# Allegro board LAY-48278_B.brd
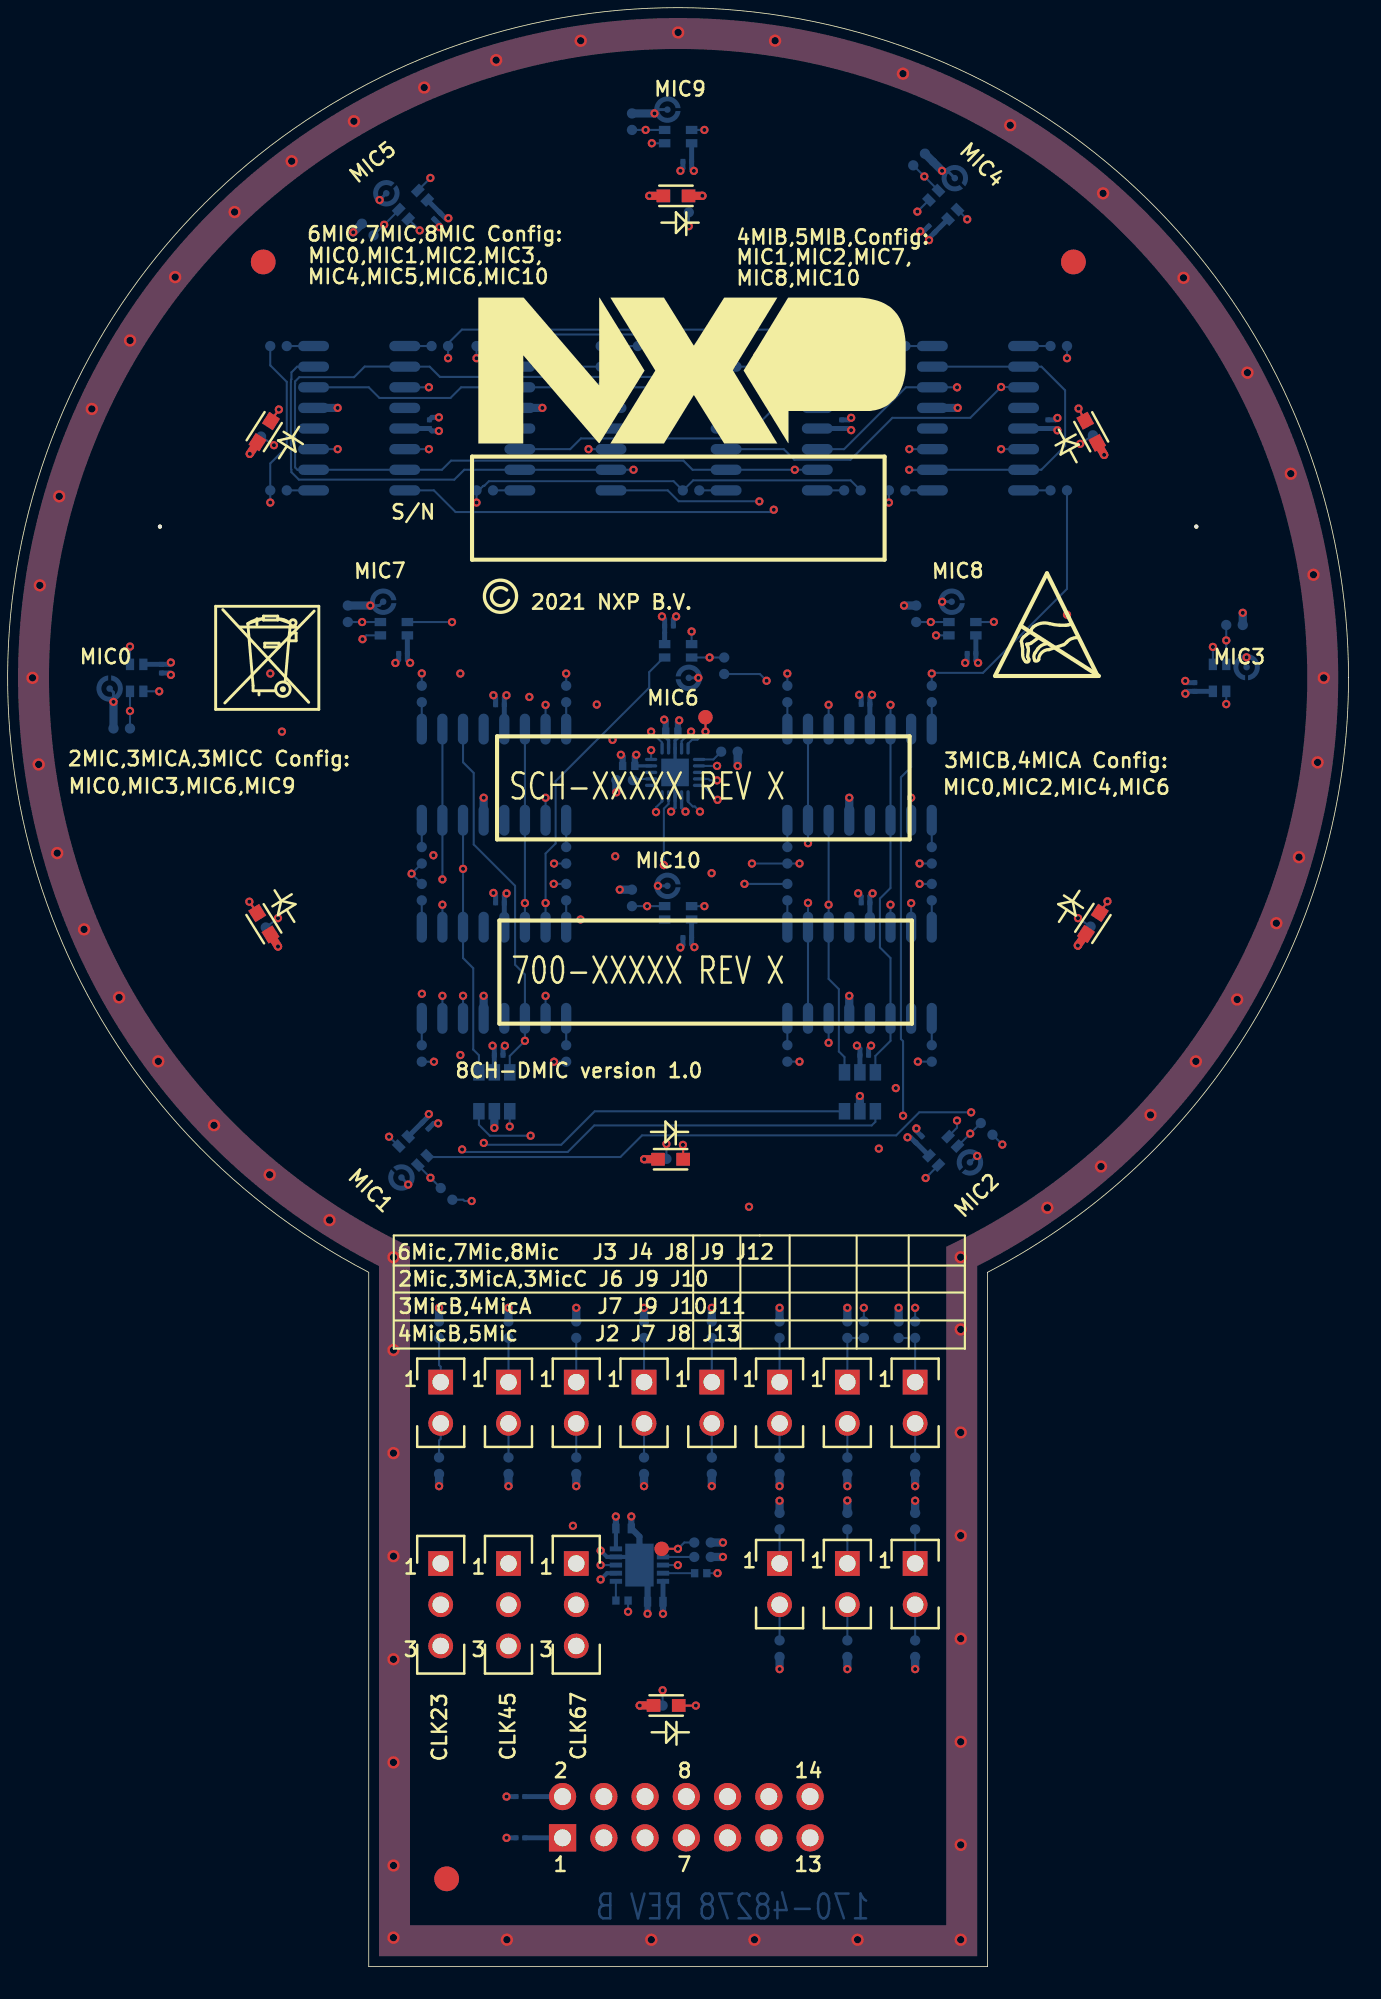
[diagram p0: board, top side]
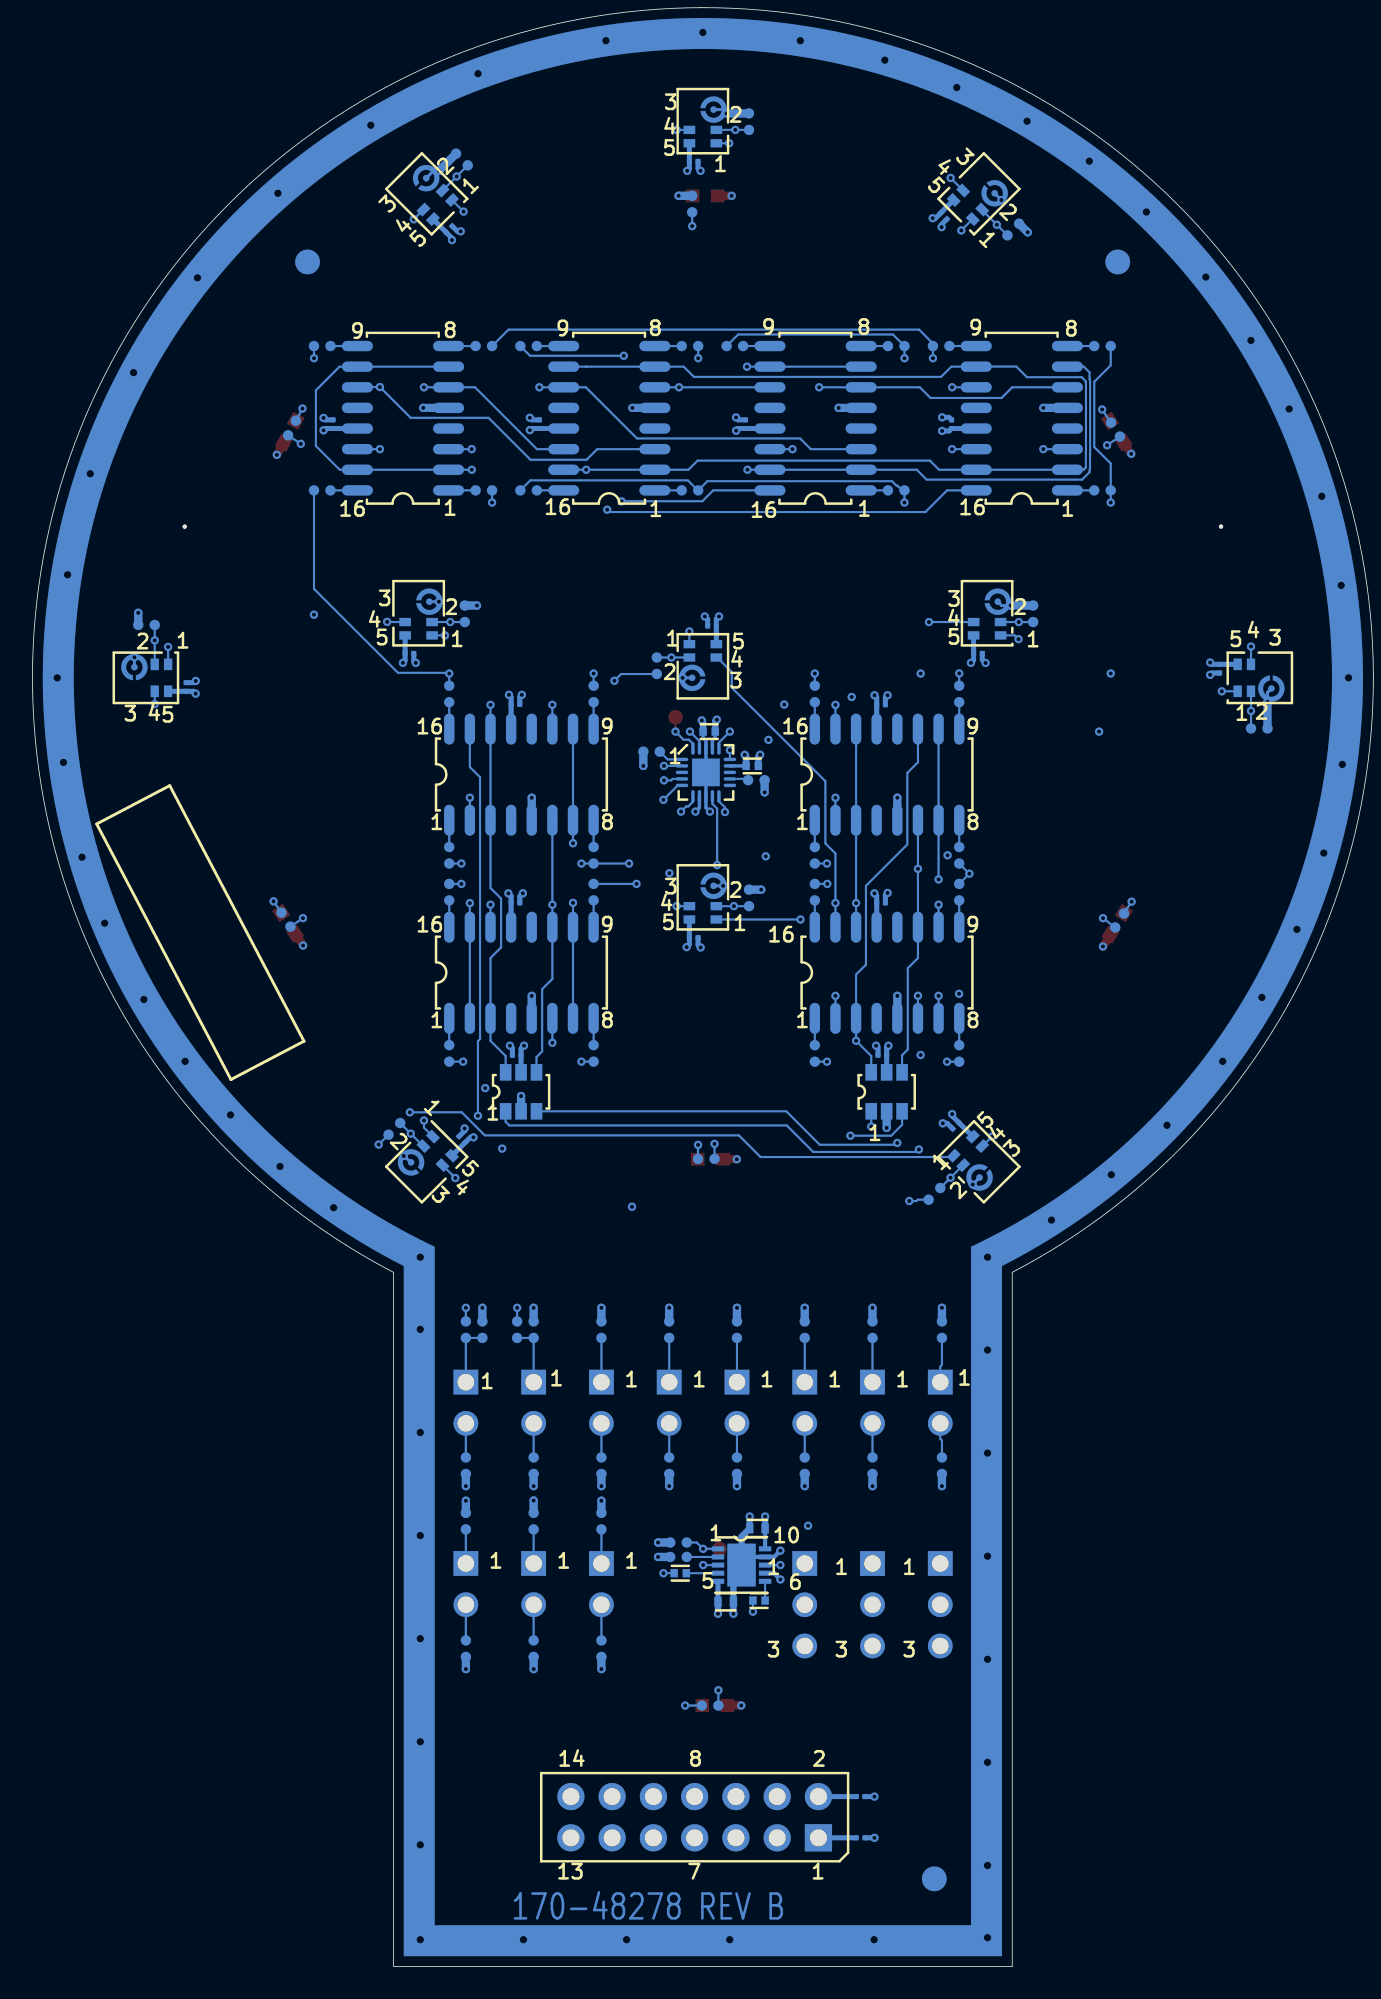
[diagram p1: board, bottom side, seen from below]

Outline 62.69 x 114.66 mm; copper layers: TOP, L2_GND_1, L3_INNER_1, L4_PWR_1, L5_PWR_2, L6_INNER_2, L7_GND_2, BOTTOM. Coordinates in mm from the lower left corner of the outline.
Outline path: 2.37,42.76 2.37,0 40.47,0 40.47,42.76 arc(56.7,57.96) 62.69,79.38 arc(0,114.66) 2.37,42.76

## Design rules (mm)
constraint set DEFAULT: min track width 0.127

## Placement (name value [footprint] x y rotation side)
C1  0.1uF  [0201_CC]  11.7 7.93 180 bottom
C2  0.1uF  [0201_CC]  11.7 10.47 180 bottom
C3  0.1uF  [0201_CC]  -10.4 79.94 270 bottom
C4  0.1uF  [0201_CC]  39.48 80.88 180 bottom
C5  0.1uF  [0201_CC]  5.85 51.79 315 bottom
C6  0.1uF  [0201_CC]  21.98 111.19 180 bottom
C7  0.1uF  [0201_CC]  36.24 50.94 45 bottom
C8  0.1uF  [0201_CC]  53.23 78.81 90 bottom
C9  0.1uF  [0201_CC]  21.98 63.38 180 bottom
C10  0.1uF  [0201_CC]  37.04 107.01 135 bottom
C11  0.1uF  [0201_CC]  6.58 107.82 225 bottom
C12  0.1uF  [0201_CC]  20.85 82.57 0 bottom
C13  0.1uF  [0201_CC]  4.48 80.88 180 bottom
C14  0.1uF  [0201_CC]  32.96 77.74 180 bottom
C15  0.1uF  [0201_CC]  44.19 95 90 bottom
C16  0.1uF  [0201_CC]  32.88 56.13 0 bottom
C17  0.1uF  [0201_CC]  31.49 95 90 bottom
C18  0.1uF  [0201_CC]  32.96 65.52 180 bottom
C19  0.1uF  [0201_CC]  10.37 56.13 0 bottom
C20  0.1uF  [0201_CC]  6.1 95 90 bottom
C21  0.1uF  [0201_CC]  10.45 65.52 180 bottom
C22  0.1uF  [0201_CC]  18.79 95 90 bottom
C23  0.1uF  [0201_CC]  10.45 77.72 180 bottom
C24  1.0UF  [0402_CC]  18.38 73.95 180 bottom
C25  1.0UF  [0402_CC]  21.03 76.06 0 bottom
C26  10uF  [CC0402_TOL0P2]  18.06 26.98 0 bottom
C27  10uF  [CC0402_TOL0P2]  20.01 22.46 180 bottom
C28  1.0UF  [0402_CC]  17.96 22.54 0 bottom
C29  1.0UF  [0402_CC]  22.81 24.23 0 bottom
D1  BLUE  [LED_0603]  -4.09 64.23 121.9 top
D2  BLUE  [LED_0603]  20.95 49.72 0 top
D3  BLUE  [LED_0603]  46.95 64.25 56.7 top
D4  BLUE  [LED_0603]  46.85 94.53 118.6 top
D5  BLUE  [LED_0603]  21.28 109.06 0 top
D6  BLUE  [LED_0603]  -4.07 94.54 57.5 top
D7  RED  [LED_0603]  20.68 16.08 0 top
J1  CON 2X7  [CON_2X7_SKT_2P54_TH]  14.3 7.93 0 bottom
J2  HDR 1X2  [HDR102]  27.66 24.82 0 top
J3  HDR 1X2  [HDR102]  31.84 24.83 0 top
J4  HDR 1X2  [HDR102]  36.01 24.83 0 top
J5  HDR_1X3  [HDR103]  6.8 24.82 0 top
J6  HDR 1X2  [HDR102]  6.8 35.99 0 top
J7  HDR 1X2  [HDR102]  10.97 35.99 0 top
J8  HDR 1X2  [HDR102]  15.14 35.99 0 top
J9  HDR 1X2  [HDR102]  19.32 35.99 0 top
J10  HDR 1X2  [HDR102]  23.49 35.99 0 top
J11  HDR 1X2  [HDR102]  27.66 35.99 0 top
J12  HDR 1X2  [HDR102]  31.84 35.99 0 top
J13  HDR 1X2  [HDR102]  36.01 35.99 0 top
J14  HDR_1X3  [HDR103]  10.97 24.82 0 top
J15  HDR_1X3  [HDR103]  15.14 24.82 0 top
NOREF  -  []  54.34 78.54 0 top
NOREF#2  -  []  21.42 79.38 90 top
NOREF#3  -  []  40.29 85.15 90 top
NOREF#4  -  []  60.26 80.75 90 top
NOREF#5  -  []  4.12 47.32 0 top
NOREF#6  -  []  18.66 27.33 90 top
NOREF#7  -  []  38.04 107.63 90 top
NOREF#8  -  []  22.7 72.75 90 top
NOREF#9  -  []  22.25 113.12 90 top
NOREF#10  -  []  22.25 65.31 90 top
NOREF#11  -  []  24.73 72.05 90 top
NOREF#12  -  []  21.73 72.05 0 top
NOREF#13  -  []  8.73 86.65 0 top
NOREF#14  -  []  4.75 81.99 90 top
NOREF#15  -  []  58.74 70.37 0 top
NOREF#16  -  []  31.19 1.58 90 top
NOREF#17  -  []  20.43 75.02 0 top
NOREF#18  -  []  38.62 108.21 90 top
NOREF#19  -  []  27 10.47 0 top
NOREF#20  -  [unnamed#2]  -4.13 104.99 0 top
NOREF#21  -  []  -408.7 -274.72 0 top
NOREF#22  -  []  -11.13 104.76 0 top
NOREF#23  -  []  38.09 82.81 0 top
NOREF#24  -  []  12.65 1.58 0 top
NOREF#25  -  []  22.79 115.47 90 top
NOREF#26  -  []  3.92 49.06 90 top
NOREF#27  -  []  6.87 47.32 90 top
NOREF#28  -  []  9.11 93.83 0 top
NOREF#29  -  []  20.59 80.63 90 top
NOREF#30  -  []  21.63 75.02 0 top
NOREF#31  -  []  2.17 109.48 0 top
NOREF#32  -  []  2.37 0 0 top
NOREF#33  -  []  20.59 113.12 0 top
NOREF#34  -  []  40.95 79.49 0 top
NOREF#35  -  []  5.97 108.81 90 top
NOREF#36  -  []  55.16 78.54 90 top
NOREF#37  -  []  -7.06 77.43 0 top
NOREF#38  -  []  37.44 49.36 0 top
NOREF#39  -  []  -376.32 243.82 0 top
NOREF#40  -  [unnamed#2]  53.32 88.69 0 top
NOREF#41  -  []  17.59 26.98 0 top
NOREF#42  -  []  20.04 67.65 0 top
NOREF#43  -  []  22.79 67.65 90 top
NOREF#44  -  []  38.72 111.43 0 top
NOREF#45  -  []  21.81 22.11 90 top
NOREF#46  -  []  37.44 109.39 0 top
NOREF#47  -  [unnamed#2]  45.76 104.99 0 top
NOREF#48  -  []  4.21 50.54 90 top
NOREF#49  -  []  22.79 78.28 0 top
NOREF#50  -  []  20.61 22.11 0 top
NOREF#51  -  []  25.54 78.28 90 top
NOREF#52  -  []  3.09 82.81 0 top
NOREF#53  -  []  4.75 82.81 90 top
NOREF#54  -  []  4.92 109.48 90 top
NOREF#55  -  []  19.54 22.46 0 top
NOREF#56  -  []  22.7 72.75 90 top
NOREF#57  -  []  4.21 108.21 0 top
NOREF#58  -  []  -13.58 79.38 90 top
NOREF#59  -  []  -12.33 78.54 90 top
NOREF#60  -  [unnamed#2]  -10.49 88.69 0 top
NOREF#61  -  []  2.54 85.15 0 top
NOREF#62  -  []  37.54 85.15 0 top
NOREF#63  -  []  -12.33 80.21 0 top
NOREF#64  -  []  7.17 5.4 0 top
NOREF#65  -  []  5.39 109.39 90 top
NOREF#66  -  []  22.25 112.3 90 top
NOREF#67  -  []  40.47 0 90 top
NOREF#68  -  []  -23.89 -50.56 0 top
NOREF#69  -  []  22.25 64.49 90 top
NOREF#70  -  []  37.44 49.36 90 top
NOREF#71  -  []  -11.92 78 90 top
NOREF#72  -  []  2.37 0 0 top
NOREF#73  -  []  20.59 65.31 0 top
NOREF#74  -  []  38.92 49.06 90 top
NOREF#75  -  []  7.17 5.4 0 top
NOREF#76  -  []  40.66 49.27 0 top
NOREF#77  -  []  10.48 84.38 0 top
NOREF#78  -  []  17.46 27.33 0 top
NOREF#79  -  []  7.17 5.4 0 top
NOREF#80  -  []  -14.67 78 0 top
NOREF#81  -  []  39.75 82.81 90 top
NOREF#82  -  []  57.51 80.75 0 top
NOREF#83  -  []  43.41 49.27 90 top
NOREF#84  -  []  20.04 115.47 0 top
NOREF#85  -  []  41.47 111.43 90 top
NOREF#86  -  []  39.75 81.99 90 top
NOREF#87  -  []  55.16 78.54 90 top
NOREF#88  -  []  29.54 7.93 90 top
NOREF#89  -  []  5.29 85.15 90 top
NOREF#90  -  []  10.41 58.08 0 top
NOREF#91  -  []  2.37 0 0 top
NOREF#92  -  []  14.3 10.47 0 top
NOREF#93  -  [unnamed#2]  7.17 5.4 0 top
NOREF#94  -  []  4.21 50.54 0 top
NOREF#95  -  []  10.27 69.42 0 top
NOREF#96  -  []  20.59 80.63 0 top
NOREF#97  -  [unnamed#2]  7.17 5.4 180 bottom
NOREF#98  -  [unnamed#2]  -4.13 104.99 180 bottom
NOREF#99  -  []  58.74 70.37 242.3 bottom
NOREF#100  -  [unnamed#2]  45.76 104.99 180 bottom
R1  100K  [RC0402_25]  27.66 19.58 90 bottom
R2  0  [RC0402_25]  -12.84 76.26 0 bottom
R3  0  [RC0402_25]  7.16 47.59 135 bottom
R4  0  [RC0402_25]  36.07 83.32 270 bottom
R5  0  [RC0402_25]  18.58 113.63 270 bottom
R6  1K  [RC0402_25]  27.66 27.43 90 bottom
R7  100K  [RC0402_25]  31.84 19.58 90 bottom
R8  0  [RC0402_25]  40.41 51.59 135 bottom
R9  0  [RC0402_25]  55.67 82.63 180 bottom
R10  0  [RC0402_25]  18.58 65.82 270 bottom
R11  1K  [RC0402_25]  31.84 27.43 90 bottom
R12  0  [RC0402_25]  36.25 111.3 225 bottom
R13  0  [RC0402_25]  2.31 106.99 315 bottom
R14  100K  [RC0402_25]  36.01 19.58 90 bottom
R15  0  [RC0402_25]  24.25 80.12 90 bottom
R16  0  [RC0402_25]  1.08 83.32 270 bottom
R17  1K  [RC0402_25]  36.01 27.43 90 bottom
R18  100K  [RC0402_25]  6.7 39.23 270 bottom
R19  100K  [RC0402_25]  10.97 39.23 270 bottom
R20  100K  [RC0402_25]  15.14 39.23 270 bottom
R21  100K  [RC0402_25]  19.32 39.23 270 bottom
R22  0  [RC0402_25]  6.74 99.81 180 bottom
R23  0  [RC0402_25]  28.14 78.38 270 bottom
R24  0  [RC0402_25]  34.9 99.81 0 bottom
R25  0  [RC0402_25]  44.85 99.81 180 bottom
R26  0  [RC0402_25]  44.85 90.92 180 bottom
R27  0  [RC0402_25]  34.9 90.92 0 bottom
R28  0  [RC0402_25]  37.03 78.38 270 bottom
R29  0  [RC0402_25]  37.03 68.45 90 bottom
R30  0  [RC0402_25]  14.52 78.38 270 bottom
R31  0  [RC0402_25]  37.03 56.24 90 bottom
R32  1K  [RC0402_25]  10.97 30.85 270 bottom
R33  1K  [RC0402_25]  6.7 30.85 270 bottom
R34  1K  [RC0402_25]  15.14 30.85 270 bottom
R35  1K  [RC0402_25]  19.32 30.85 270 bottom
R36  100K  [RC0402_25]  23.49 39.23 270 bottom
R37  100K  [RC0402_25]  27.66 39.23 270 bottom
R38  100K  [RC0402_25]  31.84 39.23 270 bottom
R39  100K  [RC0402_25]  34.99 39.23 270 bottom
R40  0  [RC0402_25]  22.21 99.81 0 bottom
R41  0  [RC0402_25]  32.15 99.81 180 bottom
R42  0  [RC0402_25]  32.15 90.92 180 bottom
R43  0  [RC0402_25]  -3.19 99.81 0 bottom
R44  0  [RC0402_25]  9.51 99.81 0 bottom
R45  0  [RC0402_25]  -3.19 90.92 0 bottom
R46  0  [RC0402_25]  14.52 66.17 270 bottom
R47  0  [RC0402_25]  28.14 66.17 270 bottom
R48  0  [RC0402_25]  22.21 90.92 0 bottom
R49  0  [RC0402_25]  36.01 39.23 90 bottom
R50  0  [RC0402_25]  19.44 99.81 180 bottom
R51  0  [RC0402_25]  5.63 56.24 90 bottom
R52  0  [RC0402_25]  9.51 90.92 0 bottom
R53  0  [RC0402_25]  14.52 68.45 90 bottom
R54  0  [RC0402_25]  32.85 39.23 90 bottom
R55  0  [RC0402_25]  5.63 78.38 270 bottom
R56  0  [RC0402_25]  28.14 68.45 90 bottom
R57  0  [RC0402_25]  28.14 56.24 90 bottom
R58  0  [RC0402_25]  5.63 66.17 270 bottom
R59  0  [RC0402_25]  37.03 66.17 270 bottom
R60  1K  [RC0402_25]  23.49 30.85 270 bottom
R61  1K  [RC0402_25]  27.66 30.85 270 bottom
R62  0  [RC0402_25]  5.63 68.45 90 bottom
R63  0  [RC0402_25]  14.52 56.24 90 bottom
R64  1K  [RC0402_25]  36.01 30.85 270 bottom
R65  1K  [RC0402_25]  31.84 30.85 270 bottom
R66  330  [RC0402_25]  -4.24 64.43 301.9 bottom
R67  330  [RC0402_25]  21.21 49.75 180 bottom
R68  330  [RC0402_25]  47.09 64.48 237.3 bottom
R69  330  [RC0402_25]  46.72 94.76 298 bottom
R70  330  [RC0402_25]  22.07 108.56 270 bottom
R71  330  [RC0402_25]  -3.99 94.66 237.5 bottom
R72  510  [RC0402_25]  20.97 16.07 180 bottom
R73  100K  [RC0402_25]  24.57 74.83 180 bottom
R74  100K  [RC0402_25]  18.12 73.07 180 bottom
R75  100K  [RC0402_25]  22.92 26.12 0 bottom
R76  100K  [RC0402_25]  22.92 25.23 180 bottom
TP1  TP_35MIL  [TESTPOINT_35MIL]  23.1 76.95 0 top
TP2  TP_35MIL  [TESTPOINT_35MIL]  20.4 25.73 0 top
U1  SPH0641LM4H-1  [MIC5_3P6X2P75MM]  -12.87 79.38 90 bottom
U2  SPH0641LM4H-1  [MIC5_3P6X2P75MM]  38.92 83.35 0 bottom
U3  SPH0641LM4H-1  [MIC5_3P6X2P75MM]  4.42 49.57 135 bottom
U4  SPH0641LM4H-1  [MIC5_3P6X2P75MM]  21.42 113.67 0 bottom
U5  SPH0641LM4H-1  [MIC5_3P6X2P75MM]  38.41 49.57 225 bottom
U6  SPH0641LM4H-1  [MIC5_3P6X2P75MM]  55.71 79.38 270 bottom
U7  SPH0641LM4H-1  [MIC5_3P6X2P75MM]  21.42 65.85 0 bottom
U8  SPH0641LM4H-1  [MIC5_3P6X2P75MM]  38.41 109.18 315 bottom
U9  SPH0641LM4H-1  [MIC5_3P6X2P75MM]  4.42 109.18 45 bottom
U10  SPH0641LM4H-1  [MIC5_3P6X2P75MM]  21.42 80.08 180 bottom
U11  SPH0641LM4H-1  [MIC5_3P6X2P75MM]  3.92 83.35 0 bottom
U12  ADG711  [SO16-25X75]  39.89 95.37 90 bottom
U13  ADG711  [SO16-25X75]  32.59 73.42 180 bottom
U14  NL27WZ16DTT1G  [TSOP6_0P95_1P7X3P1]  32.61 53.88 90 bottom
U15  ADG711  [SO16-25X75]  27.19 95.37 90 bottom
U16  ADG711  [SO16-25X75]  32.59 61.22 180 bottom
U17  NL27WZ16DTT1G  [TSOP6_0P95_1P7X3P1]  10.1 53.88 90 bottom
U18  ADG711  [SO16-25X75]  1.79 95.37 90 bottom
U19  ADG711  [SO16-25X75]  10.08 61.22 180 bottom
U20  ADG711  [SO16-25X75]  14.49 95.37 90 bottom
U21  ADG711  [SO16-25X75]  10.08 73.42 180 bottom
U22  SX1502I087TRT  [QFN20_0P4_3X3_EP067]  21.23 73.55 180 bottom
U35  MCP1256T-E/MF  [DFN_10_0P5_3X3]  19.04 24.73 180 bottom

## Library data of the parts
C1-C29 = CAP_NP
D1-D7 = LED
J1 = CONN_HDR_7X2
J2-J4 J6-J13 = CONN_HDR_2X1
J5 J14 J15 = CONN_HDR_3X1
R1-R76 = RES
TP1 TP2 = T POINT R: Tolerance: TOLERANCE; User Part Number: 510-75618
U1-U11 = MIC_SPH0641LM4H-1_5P
U12 U13 U15 U16 U18-U21 = DG711
U14 U17 = NL27WZ16_TSOP_6P
U22 = SX1502_QFN_20P
U35 = MCP1256_DFN10

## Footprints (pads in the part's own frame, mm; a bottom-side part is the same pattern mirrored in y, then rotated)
0201_CC
  rect 0.305x0.305 smd: 1(-0.267,0) 2(0.267,0)
0402_CC
  rect 0.457x0.508 smd: 1(-0.375,0) 2(0.375,0)
CC0402_TOL0P2
  rect 0.457x0.61 smd: 1(-0.475,0) 2(0.475,0)
CON_2X7_SKT_2P54_TH
  rect 1.676x1.676 hole 1.041: 1(0,0)
  round 1.676 hole 1.041: 2(0,-2.54) 3(2.54,0) 4(2.54,-2.54) 5(5.08,0) 6(5.08,-2.54) 7(7.62,0) 8(7.62,-2.54) 9(10.16,0) 10(10.16,-2.54) 11(12.7,0) 12(12.7,-2.54) 13(15.24,0) 14(15.24,-2.54)
DFN_10_0P5_3X3
  rect 0.762x0.305 smd: 1(-1.45,1) 2(-1.45,0.5) 3(-1.45,0) 4(-1.45,-0.5) 5(-1.45,-1) 6(1.45,-1) 7(1.45,-0.5) 8(1.45,0) 9(1.45,0.5) 10(1.45,1)
  rect 1.753x2.642 smd: 11(0,0)
HDR102
  rect 1.524x1.524 hole 1.016: 1(0,0)
  round 1.524 hole 1.016: 2(0,-2.54)
HDR103
  rect 1.524x1.524 hole 1.016: 1(0,0)
  round 1.524 hole 1.016: 2(0,-2.54) 3(0,-5.08)
LED_0603
  rect 0.838x0.787 smd: A(-0.775,0) C(0.775,0)
MIC5_3P6X2P75MM
  round 0 hole 0.381 unplated: (0,-0.71)
  rect 0.711x0.508 smd: 1(-0.831,1.364) 2(-0.831,0.542) 4(0.831,0.542) 5(0.831,1.364)
  custom 0.405x0.405 smd: 3(-0.66,-0.71)
QFN20_0P4_3X3_EP067
  oval 0.762x0.203 smd: 1(-1.475,0.8) 2(-1.475,0.4) 3(-1.475,0) 4(-1.475,-0.4) 5(-1.475,-0.8) 11(1.475,-0.8) 12(1.475,-0.4) 13(1.475,0) 14(1.475,0.4) 15(1.475,0.8)
  oval 0.203x0.762 smd: 6(-0.8,-1.475) 7(-0.4,-1.475) 8(0,-1.475) 9(0.4,-1.475) 10(0.8,-1.475) 16(0.8,1.475) 17(0.4,1.475) 18(0,1.475) 19(-0.4,1.475) 20(-0.8,1.475)
  rect 1.702x1.702 smd: 21(0,0)
RC0402_25
  round 0.635 smd: 1(-0.508,0) 2(0.508,0)
SO16-25X75
  oval 0.635x1.905 smd: 1(-4.445,-2.819) 2(-3.175,-2.819) 3(-1.905,-2.819) 4(-0.635,-2.819) 5(0.635,-2.819) 6(1.905,-2.819) 7(3.175,-2.819) 8(4.445,-2.819) 9(4.445,2.794) 10(3.175,2.794) 11(1.905,2.794) 12(0.635,2.794) 13(-0.635,2.794) 14(-1.905,2.794) 15(-3.175,2.794) 16(-4.445,2.794)
TESTPOINT_35MIL
  round 0.889 smd: 1(0,0)
TSOP6_0P95_1P7X3P1
  rect 1.016x0.711 smd: 1(-1.2,0.95) 2(-1.2,0) 3(-1.2,-0.95) 4(1.2,-0.95) 5(1.2,0) 6(1.2,0.95)
unnamed#2
  round 1.524 smd: (0,0)

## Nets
GND: C1.2 C2.2 C3.2 C4.2 C5.2 C6.2 C7.2 C8.2 C9.2 C10.2 C11.2 C12.2 C13.2 C14.2 C15.2 C16.2 C17.2 C18.2 C19.2 C20.2 C21.2 C22.2 C23.2 C24.2 C25.2 C26.2 C27.2 J1.11 J1.12 R2.1 R5.1 R6.2 R11.2 R12.1 R16.1 R17.2 R32.2 R33.2 R34.2 R35.2 R60.2 R61.2 R64.2 R65.2 R74.2 U1.3 U2.3 U3.3 U4.3 U5.3 U6.3 U7.3 U8.3 U9.3 U10.3 U11.3 U12.5 U13.5 U14.2 U15.5 U16.5 U17.2 U18.5 U19.5 U20.5 U21.5 U22.8 U22.18 U22.21 U35.9 U35.11
VDD: C1.1 C2.1 C3.1 C4.1 C5.1 C6.1 C7.1 C8.1 C9.1 C10.1 C11.1 C12.1 C13.1 C14.1 C15.1 C16.1 C17.1 C18.1 C19.1 C20.1 C21.1 C22.1 C23.1 C24.1 C26.1 J1.1 J1.2 R1.1 R4.1 R7.1 R9.1 R10.1 R13.1 R14.1 R18.1 R19.1 R20.1 R21.1 R36.1 R37.1 R38.1 R39.1 R73.1 R76.1 U1.5(VDD) U2.5(VDD) U3.5(VDD) U4.5(VDD) U5.5(VDD) U6.5(VDD) U7.5(VDD) U8.5(VDD) U9.5(VDD) U10.5(VDD) U11.5(VDD) U12.13(VDD) U13.13(VDD) U14.5(VCC) U15.13(VDD) U16.13(VDD) U17.5(VCC) U18.13(VDD) U19.13(VDD) U20.13(VDD) U21.13(VDD) U22.14(VDDM) U35.7 U35.10
VDD_3V3: C25.1 C27.1 D1.A D2.A D3.A D4.A D5.A D6.A D7.A R75.2 U22.7 U22.17 U35.5(VOUT)
CLK01: J1.3 J5.1 J14.1 U14.1
CLK01_S1: R29.2 U13.1
CLK01_S2: R28.2 U13.16
CLK01_S3: R23.2 U13.9
CLK01_S4: R31.2 U16.1
CLK23: J1.5 J5.3
CLK23_S1: R56.2 U13.8
CLK23_S2: R59.2 U16.16
CLK23_S3: R47.2 U16.9
CLK23_S4: R46.2 U19.16
CLK23_S5: R51.2 U19.8
CLK23_S6: R53.2 U21.1
CLK23_S7: R30.2 U21.16
CLK45: J1.7 J14.3
CLK45_S1: R57.2 U16.8
CLK45_S2: R63.2 U19.1
CLK45_S3: R55.2 U21.9
CLK67: J1.9 J15.3
CLK67_S1: R58.2 U19.9
CLK67_S2: R62.2 U21.8
CLK_MIC0: U1.4 U13.2
CLK_MIC1: U3.4 U13.15
CLK_MIC2: U5.4 U13.7 U13.10
CLK_MIC3: U6.4 U16.2 U16.15
CLK_MIC4: U8.4 U16.7 U16.10
CLK_MIC5: U9.4 U19.2
CLK_MIC6: U10.4 U19.10 U19.15
CLK_MIC7: U11.4 U19.7
CLK_MIC8: U2.4 U21.2
CLK_MIC9: U4.4 U21.15
CLK_MIC10: U7.4 U21.7 U21.10
CLKBUF_01: U13.3 U13.11 U13.14 U14.6 U16.3
CLKBUF_23: U13.6 U14.4 U16.11 U16.14 U19.6 U19.14 U21.3 U21.14
CLKBUF_45: U16.6 U17.6 U19.3 U21.11
CLKBUF_67: U17.4 U19.11 U21.6
DATA01: J1.4 U12.2 U12.7 U12.10 U12.15
DATA01_S1: R27.2 U12.1
DATA01_S2: R26.2 U12.16
DATA01_S3: R25.2 U12.9
DATA01_S4: R24.2 U12.8
DATA23: J1.6 U15.2 U15.7 U15.10 U15.15 U18.2 U18.10 U18.15
DATA23_S1: R48.2 U15.1
DATA23_S2: R42.2 U15.16
DATA23_S3: R41.2 U15.9
DATA23_S4: R40.2 U15.8
DATA23_S5: R45.2 U18.1
DATA23_S6: R49.2 U18.16
DATA23_S7: R22.2 U18.9
DATA45: J1.8 U18.7 U20.2 U20.15
DATA45_S1: R43.2 U18.8
DATA45_S2: R52.2 U20.1
DATA45_S3: R54.2 U20.16
DATA67: J1.10 U20.7 U20.10
DATA67_S1: R50.2 U20.9
DATA67_S2: R44.2 U20.8
DATA_MIC0: U1.1 U12.3
DATA_MIC1: U3.1 U12.14
DATA_MIC2: U5.1 U12.11 U15.3
DATA_MIC3: U6.1 U12.6 U15.14
DATA_MIC4: U8.1 U15.11 U20.3
DATA_MIC5: U9.1 U20.14
DATA_MIC6: U10.1 U15.6 U20.11
DATA_MIC7: U11.1 U18.3
DATA_MIC8: U2.1 U18.14
DATA_MIC9: U4.1 U18.11
DATA_MIC10: U7.1 U18.6 U20.6
I2C_SCL: J1.13 U22.4
I2C_SDA: J1.14(B7) U22.2
N48973005: J6.1 R18.2 R22.1 R24.1 R30.1 R31.1
N48973061: J6.2 R33.1
N48974373: J7.1 R19.2 R23.1 R25.1
N48974457: J7.2 R32.1
N48975829: J8.1 R20.2 R26.1 R28.1
N48975969: J8.2 R34.1
N48976451: J9.1 R21.2 R27.1 R29.1
N48976531: J9.2 R35.1
N48977082: J10.1 R36.2 R40.1 R46.1
N48977084: J11.1 R37.2 R41.1 R47.1
N48977086: J12.1 R38.2 R42.1 R44.1 R48.1 R50.1 R52.1 R54.1 R56.1 R57.1 R58.1 R59.1 R62.1 R63.1
N48977088: J13.1 R39.2 R43.1 R45.1 R49.1 R51.1 R53.1 R55.1
N48977384: J10.2 R60.1
N48977390: J11.2 R61.1
N48977416: J12.2 R65.1
N48977422: J13.2 R64.1
N48994161: C29.1 U35.4
N48994166: C29.2 U35.8
N48994180: C28.1 U35.6
N48994185: C28.2 U35.3
N48994280: R75.1 TP2.1(TP) U35.1
N48994390: R76.2 U35.2
N48994989: R73.2 U22.1
N48996748: D1.C(CATHODE) R66.1
N48996751: D2.C(CATHODE) R67.1
N48996754: D3.C(CATHODE) R68.1
N48996757: D4.C(CATHODE) R69.1
N48996760: D5.C(CATHODE) R70.1
N48996763: D6.C(CATHODE) R71.1
N48996766: D7.C(CATHODE) R72.1
N48996769: R66.2 U22.5
N48996774: R67.2 U22.6
N48996779: R68.2 U22.9
N48996784: R69.2 U22.10
N48996789: R70.2 U22.15
N48996794: R71.2 U22.16
N48996799: R72.2 U22.19
N48996815: TP1.1(TP) U22.20
N48996848: R74.1 U22.12
N49015950: R2.2 U1.2
N49016109: R9.2 U6.2
N49016339: R12.2 U8.2
N49016430: R13.2 U9.2
N49016833: R4.2 U2.2
N49016924: R5.2 U4.2
N49017156: R10.2 U7.2
N49017523: J2.2 R1.2 R3.1
N49017528: J2.1 R6.1
N49017613: R3.2 U3.2
N49017928: J3.2 R7.2 R8.1
N49017933: J3.1 R11.1
N49018011: R8.2 U5.2
N49018485: J4.2 R14.2 R15.1
N49018490: J4.1 R17.1
N49018577: R15.2 U10.2
N49018582: J5.2 U14.3
N49022344: R16.2 U11.2
N49072543: J14.2 J15.1 U17.1
N49072589: J15.2 U17.3

Pads without a net: U12 4 12; U13 4 12; U15 4 12; U16 4 12; U18 4 12; U19 4 12; U20 4 12; U21 4 12; U22 3 11 13

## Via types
v1: diameter 0.508, hole 0.254, TOP to BOTTOM, 262 vias
v2: diameter 0.762, hole 0.457, TOP to BOTTOM, 58 vias

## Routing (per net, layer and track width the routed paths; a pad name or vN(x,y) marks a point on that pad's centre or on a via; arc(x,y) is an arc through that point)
GND: length 83.1
  L2_GND_1 w0.177: 27,6.9 J1.11 ; J1.11 27,8.96 ; J1.11 25.97,7.93 ; J1.11 28.03,7.93 ; 27,9.44 J1.12 ; J1.12 25.97,10.47 ; J1.12 27,11.5 ; J1.12 28.03,10.47
  L7_GND_2 w0.177: 27,9.44 J1.12 ; J1.12 27,11.5 ; J1.12 25.97,10.47 ; J1.12 28.03,10.47 ; J1.11 28.03,7.93 ; J1.11 25.97,7.93 ; J1.11 27,6.9 ; J1.11 27,8.96
  BOTTOM w0.177: v1(3.04,108.81) U9.3 ; U6.3 v1(56.42,80.64) ; U3.3 v1(4.8,48.16)
  BOTTOM w0.178: U7.3 v1(20.17,66.56) ; v1(37.67,110.61) 38,110.61 U8.3 ; U2.3 v1(37.67,84.06) ; v1(-13.35,77.89) -13.35,78.48 U1.3 ; U5.3 v1(39.83,49.93) ; v1(19.96,114.14) 20.2,114.37 U4.3 ; U10.3 v1(22.66,79.38) ; U11.3 3.02,83.83 v1(2.46,83.83)
  BOTTOM w0.203: v1(20.98,71.14) 21.23,71.38 U22.8 U22.21 U22.18 21.23,75.51 21.4,75.69 C25.2
  BOTTOM w0.254: v1(16.65,25.62) 17.03,25.23 U35.9 18.54,25.23 U35.11
  BOTTOM w0.305: C21.2 10.18,65.99 v1(10.04,66.13) ; C19.2 10.63,56.6 v1(10.75,56.71) ; C22.2 19.23,95.26 v1(19.38,95.41) ; C10.2 36.53,106.88 v1(36.33,106.88) ; v1(33.3,56.72) 33.14,56.57 C16.2 ; C4.2 39.21,80.42 v1(39.09,80.3) ; C15.2 44.65,95.26 v1(44.77,95.38) ; v1(36.09,51.62) 36.09,51.47 C7.2 ; v1(32.07,95.39) 31.94,95.26 C17.2 ; C20.2 6.26,95.42 v1(6.69,95.42) ; v1(21.55,62.77) 21.71,62.93 C9.2 ; v1(6.64,51.94) 6.37,51.94 C5.2 ; v1(21.29,83.15) 21.12,82.98 C12.2 ; v1(10.04,78.3) 10.18,78.16 C23.2 ; v1(6.72,107.13) 6.72,107.3 C11.2 ; C8.2 52.75,79.08 v1(52.64,79.19) ; C18.2 32.69,65.91 v1(32.5,66.1) ; C1.2 v1(10.85,7.93) ; v1(4.01,80.29) 4.21,80.49 C13.2 ; v1(-9.81,79.56) -9.93,79.67 C3.2 ; C6.2 21.71,110.76 v1(21.56,110.6) ; C14.2 32.69,78.2 v1(32.56,78.33) ; C2.2 v1(10.85,10.47)
  BOTTOM w0.381: C24.2 18,74.53 v1(17.89,74.64) ; v1(18.54,27.72) C26.2 19.04,26.48 U35.11 19.54,24.23 C27.2 v1(19.54,21.73) ; v1(21.48,76.76) 21.4,76.68 C25.2
  BOTTOM w0.508: R5.1 v1(19.96,114.14) ; U18.5 v1(0.45,96) ; U13.5 v1(31.95,71.99) ; R74.2 v1(17.62,72.32) ; R32.2 v1(10.97,29.59) ; U12.5 v1(38.63,96) ; R2.1 v1(-13.35,77.89) ; R11.2 v1(31.84,28.7) ; R65.2 v1(31.84,29.59) ; R17.2 v1(36.01,28.69) ; R34.2 v1(15.14,29.59) ; R64.2 v1(36.01,29.59) ; R35.2 v1(19.32,29.59) ; R60.2 v1(23.49,29.59) ; U17.2 v1(10.1,51.65) ; U14.2 v1(32.61,53.62) ; U20.5 v1(13.06,96) ; v1(37.67,110.61) 37.11,111.17 R12.1 ; R6.2 v1(27.66,28.69) ; R61.2 v1(27.66,29.59) ; v1(2.46,83.83) R16.1 ; U19.5 v1(9.44,59.79) ; U16.5 v1(31.95,59.79) ; U21.5 v1(9.44,71.99) ; R33.2 v1(6.7,29.59) ; U15.5 v1(25.76,96)
  vias: v1(14.94,27.15) v2(-18.33,79.38) v2(-17.95,74.04) v2(-17.88,85.07) v2(-16.81,68.58) v2(-16.69,90.56) v2(-15.16,63.88) v2(-14.68,95.94) v2(-13,59.69) v2(-12.33,100.15) v2(-10.59,55.75) v2(-9.55,104.06) v2(-7.16,51.82) v2(-5.89,108.07) v2(-3.73,48.77) v2(-2.38,111.2) v2(-0.05,45.97) v2(1.46,113.66) v2(3.89,43.69) v2(3.89,37.97) v2(3.89,31.62) v2(3.89,25.27) v2(3.89,18.92) v2(3.89,12.57) v2(3.89,6.22) v2(3.89,1.78) v2(5.78,115.73) v2(10.21,117.42) v2(10.88,1.65) v2(15.42,118.62) v2(19.77,1.65) v2(21.42,119.13) v2(26.12,1.65) v2(27.39,118.62) v2(32.47,1.65) v2(35.26,116.59) v2(38.82,43.69) v2(38.82,39.24) v2(38.82,32.89) v2(38.82,26.54) v2(38.82,20.19) v2(38.82,13.84) v2(38.82,7.49) v2(38.82,1.65) v2(41.86,113.41) v2(44.15,46.74) v2(47.45,49.28) v2(47.58,109.22) v2(50.5,52.45) v2(52.53,104.01) v2(53.29,55.75) v2(55.83,59.56) v2(56.47,98.17) v2(58.25,64.26) v2(59.14,91.95) v2(59.64,68.33) v2(60.53,85.72) v2(60.79,74.17) v2(61.17,79.38)
VDD: length 71.5
  L4_PWR_1 w0.127: 13.27,7.93 J1.1 ; J1.1 14.3,8.96 ; J1.1 14.3,6.9 ; J1.1 15.33,7.93 ; 13.27,10.47 J1.2 ; J1.2 15.33,10.47 ; J1.2 14.3,11.5 ; J1.2 14.3,9.44
  BOTTOM w0.203: C24.1 U22.14
  BOTTOM w0.254: v1(16.65,23.84) 17.03,24.23 U35.7 ; C26.1 U35.10
  BOTTOM w0.305: v1(19.37,94.6) 19.37,94.62 19.26,94.73 C22.1 U20.13 ; U2.5 C4.1 39.75,80.43 v1(39.88,80.3) ; U9.5 6.77,108.01 C11.1 7.09,107.69 v1(7.27,107.69) ; U13.13 C14.1 33.22,78.19 v1(33.36,78.33) ; U16.13 C18.1 33.22,65.93 v1(33.39,66.1) ; v1(22.42,62.79) 22.25,62.96 C9.1 U7.5 ; U11.5 C13.1 4.75,80.46 v1(4.91,80.3) ; v1(6.07,52.51) 6.07,52.39 C5.1 4.8,51.12 ; C2.1 J1.2 ; U1.5 C3.1 -9.93,80.21 v1(-9.81,80.32) ; v1(35.54,51.07) 35.73,51.07 C7.1 36.05,50.75 U5.5 ; v1(9.99,56.71) 10.1,56.6 C19.1 U17.5 ; U4.5 C6.1 22.25,110.74 v1(22.38,110.6) ; v1(44.77,94.62) 44.66,94.73 C15.1 U12.13 ; v1(6.69,94.58) 6.25,94.58 C20.1 U18.13 ; U14.5 C16.1 32.61,56.54 v1(32.43,56.72) ; v1(52.64,78.4) 52.79,78.54 C8.1 U6.5 ; U10.5 20.59,82.14 20.59,82.14 C12.1 20.59,82.99 v1(20.42,83.15) ; v1(10.85,78.3) 10.71,78.17 C23.1 U21.13 ; v1(36.86,106.34) 36.86,106.46 C10.1 37.23,106.82 U8.5 ; U15.13 C17.1 31.97,94.73 v1(32.07,94.63) ; U19.13 C21.1 10.71,65.96 v1(10.86,66.1) ; C1.1 J1.1
  BOTTOM w0.381: v1(17.59,27.72) C26.1 ; C24.1 18.75,74.55 v1(18.84,74.64)
  BOTTOM w0.508: R37.1 v1(27.66,40.57) ; R19.1 v1(10.97,40.57) ; R13.1 v1(1.42,106.82) ; R76.1 v1(24.18,25.23) ; R38.1 v1(31.84,40.57) ; R18.1 v1(6.7,40.57) ; R4.1 v1(35.33,83.83) ; R39.1 v1(34.99,40.57) ; R1.1 v1(27.66,18.32) ; R14.1 v1(36.01,18.32) ; R21.1 v1(19.32,40.57) ; R73.1 v1(25.08,73.95) ; R20.1 v1(15.14,40.57) ; R36.1 v1(23.49,40.57) ; R7.1 v1(31.84,18.32) ; R9.1 v1(56.18,83.38) ; R10.1 v1(17.83,66.33)
VDD_3V3: length 11.7
  TOP w0.508: D1.A v1(-3.22,62.83) ; D6.A v1(-4.96,93.17) ; D4.A v1(47.65,93.11) ; D3.A 46.52,63.6 46.03,62.89 v1(46.03,62.89) ; D2.A v1(19.33,49.72) ; D5.A v1(19.65,109.06) ; D7.A v1(19.05,16.08)
  BOTTOM w0.203: C25.1 20.65,75.71 20.83,75.54 U22.17 ; U22.7 21.63,71.38 v1(21.87,71.14)
  BOTTOM w0.305: U35.5 C27.1
  BOTTOM w0.381: v1(20.56,76.8) 20.65,76.7 C25.1 ; C27.1 v1(20.49,21.73)
  BOTTOM w0.508: R75.2 v1(24.18,26.12)
CLK01: length 76.5
  L3_INNER_1 w0.127: J5.1 8.12,26.14 v1(8.12,50.33) ; J14.1 12.79,23 12.79,17.79 15.59,15 15.59,9.16 16.82,7.93 J1.3
  L6_INNER_2 w0.127: J5.1 J14.1
  BOTTOM w0.127: U14.1 33.56,52.03 33.34,51.81 16.25,51.81 14.62,50.17 8.28,50.17 8.12,50.33 v1(8.12,50.33)
CLK01_S1: length 1.7
  BOTTOM w0.127: U13.1 R29.2
CLK01_S2: length 1.7
  BOTTOM w0.127: U13.16 R28.2
CLK01_S3: length 1.7
  BOTTOM w0.127: U13.9 28.14,77.87 R23.2
CLK01_S4: length 1.7
  BOTTOM w0.127: R31.2 U16.1
CLK23: length 21
  L6_INNER_2 w0.127: J1.5 18.07,9.24 11.32,9.24 6.8,13.76 J5.3
CLK23_S1: length 1.7
  BOTTOM w0.127: U13.8 R56.2
CLK23_S2: length 1.7
  BOTTOM w0.127: R59.2 U16.16
CLK23_S3: length 1.7
  BOTTOM w0.127: R47.2 U16.9
CLK23_S4: length 1.7
  BOTTOM w0.127: U19.16 R46.2
CLK23_S5: length 1.7
  BOTTOM w0.127: U19.8 R51.2
CLK23_S6: length 1.7
  BOTTOM w0.127: R53.2 U21.1
CLK23_S7: length 1.7
  BOTTOM w0.127: U21.16 R30.2
CLK45: length 24.2
  L3_INNER_1 w0.127: J1.7 20.82,6.82 13.11,6.82 9.59,10.34 9.59,18.37 J14.3
CLK45_S1: length 1.7
  BOTTOM w0.127: R57.2 U16.8
CLK45_S2: length 1.7
  BOTTOM w0.127: R63.2 U19.1
CLK45_S3: length 1.7
  BOTTOM w0.127: U21.9 R55.2
CLK67: length 18.1
  L6_INNER_2 w0.127: J1.9 24.46,7.96 23.14,9.29 18.92,9.29 18.19,10.02 18.19,16.7 J15.3
CLK67_S1: length 1.7
  BOTTOM w0.127: R58.2 U19.9
CLK67_S2: length 1.7
  BOTTOM w0.127: U21.8 R62.2
CLK_MIC0: length 57.1
  L6_INNER_2 w0.127: v1(-12.33,81.3) -12.33,78.16 -5.64,71.46 18.47,71.46 19.5,72.5 35.25,72.5 v1(35.76,71.99)
  BOTTOM w0.127: U13.2 v1(35.76,71.99) ; U1.4 v1(-12.33,81.3)
CLK_MIC1: length 77.3
  L6_INNER_2 w0.127: v1(35.27,52.4) 31.51,52.4 31.38,52.28 31.38,51.48 31.25,51.35 31,51.35 30.87,51.48 30.87,53.33 30.75,53.45 30.49,53.45 30.37,53.33 30.37,51.48 30.24,51.35 29.98,51.35 29.86,51.48 29.86,53.33 29.73,53.45 29.48,53.45 29.35,53.33 29.35,51.48 29.22,51.35 28.97,51.35 28.84,51.48 28.84,53.33 28.71,53.45 28.46,53.45 28.33,53.33 28.33,51.48 28.21,51.35 27.95,51.35 27.83,51.48 27.83,53.33 27.7,53.45 27.44,53.45 27.32,53.33 27.32,51.48 27.19,51.35 26.94,51.35 26.81,51.48 26.81,53.33 26.68,53.45 26.43,53.45 26.3,53.33 26.3,52.61 26.09,52.4 15.05,52.4 12.77,50.13 9.07,50.13 8.09,51.11 v1(3.62,51.11)
  BOTTOM w0.127: U3.4 v1(3.62,51.11) ; v1(35.27,52.4) 35.27,56.99 35.14,57.13 35.14,73.25 35.76,73.88 U13.15
CLK_MIC2: length 67.9
  L3_INNER_1 w0.127: v1(36.66,48.57) 36.66,50.52 37.13,50.99 37.13,56.85 36.35,57.62 36.35,57.8 36.93,58.38 36.93,58.55 36.75,58.73 36.56,58.73 36,58.16 35.82,58.16 35.64,58.34 35.64,58.52 36.87,59.76 36.87,59.98 36.72,60.14 36.54,60.14 35.28,58.88 35.1,58.88 34.81,59.17 34.81,59.35 36.24,60.78 36.24,60.96 36.08,61.13 35.87,61.13 34.45,59.71 34.27,59.71 34.09,59.89 34.09,60.07 35.53,61.5 35.53,61.68 35.36,61.85 35.15,61.85 33.73,60.43 33.55,60.43 33.37,60.6 33.37,60.78 34.81,62.22 34.81,62.4 34.64,62.57 34.43,62.57 33.01,61.14 32.83,61.14 32.65,61.32 32.65,61.5 34.09,62.94 34.09,63.12 33.92,63.28 33.71,63.28 32.29,61.86 32.11,61.86 31.93,62.04 31.93,62.22 33.37,63.66 33.37,63.84 33.2,64 33,64 31.58,62.58 31.4,62.58 31.22,62.76 31.22,62.94 32.65,64.38 32.65,64.56 32.48,64.72 32.28,64.72 30.86,63.3 30.68,63.3 30.5,63.48 30.5,63.66 31.93,65.09 31.93,65.27 31.76,65.44 31.56,65.44 30.14,64.02 29.96,64.02 28.93,65.05 28.93,65.93 29.41,66.41 v1(29.41,69.19)
  BOTTOM w0.127: v1(29.41,69.19) U13.7 U13.10 ; U5.4 36.88,48.78 v1(36.66,48.57)
CLK_MIC3: length 37.9
  L6_INNER_2 w0.127: v1(55.16,77.76) 55.16,68.93 51.28,65.04 46.92,65.04 46.46,65.5 v1(35.76,65.5)
  BOTTOM w0.127: U6.4 v1(55.16,77.76) ; v1(35.76,65.5) U16.15 U16.2
CLK_MIC4: length 54.1
  L3_INNER_1 w0.127: v1(39.22,107.62) 39.22,99.61 33.98,94.37 33.98,92.99 32.02,91.03 32.02,75.01 31.33,74.32 31.33,67.44 v1(29.41,65.51)
  BOTTOM w0.127: U8.4 v1(39.22,107.62) ; U16.7 U16.10 v1(29.41,65.51)
CLK_MIC5: length 55.8
  L3_INNER_1 w0.127: v1(6.16,110.16) 10.99,105.34 10.99,94.74 12.78,92.95 12.78,64.08 13.25,63.61 v1(13.25,59.79)
  BOTTOM w0.127: v1(6.16,110.16) 5.39,109.39 U9.4 ; U19.2 v1(13.25,59.79)
CLK_MIC6: length 27.9
  L6_INNER_2 w0.127: v1(6.9,65.4) 10.98,65.4 11.56,65.99 12.77,65.99 v1(13.25,65.5)
  BOTTOM w0.127: U10.4 20.53,80.63 19.64,79.73 19.64,78.77 13.87,73.01 13.87,69.18 13.25,68.56 v1(13.25,65.5) U19.15 ; U19.10 v1(6.9,65.4)
CLK_MIC7: length 27.4
  L3_INNER_1 w0.127: v1(7.5,82.81) 7.5,64.93 6.9,64.34 v1(6.9,59.79)
  BOTTOM w0.127: v1(7.5,82.81) 7.49,82.81 U11.4 ; U19.7 v1(6.9,59.79)
CLK_MIC8: length 38.2
  L6_INNER_2 w0.127: v1(13.25,71.99) 14.71,73.44 19.64,73.44 21.31,75.11 39.35,75.11 40.86,76.61 v1(40.86,82.82)
  BOTTOM w0.127: U2.4 40.85,82.81 v1(40.86,82.82) ; U21.2 v1(13.25,71.99)
CLK_MIC9: length 41.7
  L3_INNER_1 w0.127: v1(13.25,77.71) 13.25,91.67 13.79,92.2 13.79,103.88 v1(23.03,113.12)
  BOTTOM w0.127: U21.15 v1(13.25,77.71) ; U4.4 v1(23.03,113.12)
CLK_MIC10: length 54.2
  L6_INNER_2 w0.127: v1(23.03,65.31) 22.08,65.31 21.95,65.44 21.95,65.74 21.81,65.89 21.57,65.89 21.45,65.76 21.45,64.45 21.32,64.32 21.07,64.32 20.94,64.46 20.94,66.02 20.78,66.18 20.56,66.18 20.43,66.05 20.43,64.45 20.3,64.32 20.02,64.32 19.89,64.46 19.89,65.95 19.76,66.08 19.51,66.08 19.38,65.95 19.38,64.45 19.25,64.32 19.01,64.32 18.87,64.46 18.87,66.61 18.71,66.77 18.49,66.77 18.36,66.65 18.36,64.4 18.24,64.27 17.86,64.27 17.73,64.4 17.73,65.73 17.6,65.86 17.35,65.86 17.22,65.73 17.22,64.4 17.1,64.27 16.69,64.27 16.56,64.4 16.56,66.76 16.43,66.88 16.18,66.88 16.05,66.76 16.05,65.07 15.92,64.94 15.67,64.94 15.54,65.07 15.54,66.76 15.42,66.88 15.16,66.88 15.04,66.76 15.04,65.44 14.91,65.31 14.27,65.31 13.18,66.39 12.29,66.39 12.17,66.52 12.17,67.41 12.04,67.54 11.78,67.54 11.66,67.41 11.66,66.71 11.53,66.59 11.28,66.59 11.15,66.71 11.15,67.41 11.02,67.54 10.77,67.54 10.64,67.41 10.64,66.71 10.51,66.59 10.26,66.59 10.13,66.71 10.13,67.24 9.99,67.39 9.38,67.39 8.95,66.96 v1(6.9,66.96)
  BOTTOM w0.127: v1(6.9,66.96) U21.7 U21.10 ; U7.4 v1(23.03,65.31)
CLKBUF_01: length 28.9
  L6_INNER_2 w0.127: v1(30.68,77.71) 34.49,77.71 v1(34.49,77.71)
  BOTTOM w0.127: v1(34.49,77.71) U13.14 U13.3 34.49,66.43 33.84,65.78 33.84,62.77 34.49,62.12 U16.3 34.49,57.02 33.56,56.08 U14.6 ; U13.11 v1(30.68,77.71)
CLKBUF_23: length 61.9
  L3_INNER_1 w0.127: v1(8.17,59.79) 8.17,61.69 v1(11.98,65.5)
  L6_INNER_2 w0.127: v1(34.49,65.4) v1(30.68,65.4) 29.3,64.02 13.46,64.02 v1(11.98,65.5)
  BOTTOM w0.127: U19.14 v1(11.98,65.5) U21.3 U21.14 ; U16.14 v1(34.49,65.4) ; U13.6 v1(30.68,65.4) U16.11 30.68,60.83 31.31,60.2 31.31,56.36 31.66,56.02 U14.4 ; U19.6 v1(8.17,59.79)
CLKBUF_45: length 43.4
  L6_INNER_2 w0.127: v1(11.98,57.02) 12.11,56.9 v1(30.68,56.9)
  BOTTOM w0.127: U17.6 11.05,56.08 v1(11.98,57.02) U19.3 11.98,61.1 11.38,61.7 11.38,66.56 8.83,69.11 8.83,73.52 8.17,74.17 U21.11 ; U16.6 v1(30.68,56.9)
CLKBUF_67: length 15.9
  BOTTOM w0.127: U21.6 v1(8.17,67.61) U19.11 8.17,62.12 8.8,61.49 8.8,56.48 9.15,56.13 U17.4
DATA01: length 128
  L3_INNER_1 w0.127: J1.4 18.31,8.99 24.99,8.99 25.51,8.47 25.51,7.34 26.33,6.52 30.89,6.52 36.97,12.6 36.97,47.05 37.53,47.61 37.53,50.61 37.64,50.72 37.64,77.85 35.8,79.69 35.8,92.04 v1(35.65,92.19)
  BOTTOM w0.127: U12.7 U12.10 43.79,98.54 45.24,97.08 45.24,93.66 43.78,92.19 U12.15 U12.2 v1(35.65,92.19)
DATA01_S1: length 1.7
  BOTTOM w0.127: R27.2 U12.1
DATA01_S2: length 1.7
  BOTTOM w0.127: R26.2 U12.16
DATA01_S3: length 1.7
  BOTTOM w0.127: R25.2 U12.9
DATA01_S4: length 1.7
  BOTTOM w0.127: U12.8 R24.2
DATA23: length 175.7
  L3_INNER_1 w0.127: v1(28.6,92.19) 26.97,90.56 26.97,90.1 26.35,89.49 26.35,76.13 26.8,75.68 26.8,63.41 31.68,58.53 31.68,56.21 33.41,54.48 33.41,51.9 34.36,50.95 34.36,48.65 34.18,48.47 34.18,10.4 30.55,6.77 26.64,6.77 25.95,7.46 25.95,8.53 25.05,9.43 20.34,9.43 19.38,10.39 J1.6
  BOTTOM w0.127: U15.15 v1(28.6,92.19) U15.2 22.31,92.19 21.74,92.75 7.44,92.75 6.87,92.19 U18.15 U18.2 -2.02,92.19 -2.16,92.33 -2.16,93.24 -2.17,93.25 -2.17,97.48 -2.16,97.49 -2.16,97.64 -1.91,97.89 1.46,97.89 2.12,98.55 4.58,98.55 U18.10 6.12,98.54 6.75,97.91 21.97,97.91 22.6,98.54 U15.7 28.58,98.54 28.58,98.54 28.62,98.54 28.63,98.54 U15.10
DATA23_S1: length 1.7
  BOTTOM w0.127: R48.2 U15.1
DATA23_S2: length 1.7
  BOTTOM w0.127: R42.2 U15.16
DATA23_S3: length 1.7
  BOTTOM w0.127: R41.2 U15.9
DATA23_S4: length 1.7
  BOTTOM w0.127: R40.2 U15.8
DATA23_S5: length 1.7
  BOTTOM w0.127: U18.1 R45.2
DATA23_S6: length 77.5
  L3_INNER_1 w0.127: v1(36.01,40.57) 36.01,50.64 36.65,51.28 36.65,54.29 35.68,55.25 35.68,57.31 27.68,65.31 27.68,89.35 v1(27.31,89.73)
  BOTTOM w0.127: v1(27.31,89.73) 27.17,89.59 7.71,89.59 6.38,90.92 U18.16 ; R49.2 v1(36.01,40.57)
DATA23_S7: length 1.7
  BOTTOM w0.127: R22.2 U18.9
DATA45: length 112.5
  L3_INNER_1 w0.127: v1(18.67,92.19) 18.37,91.89 18.37,74.39 19.12,73.64 19.12,66.36 19.75,65.73 19.75,50.25 21.82,48.19 21.82,27.1 21.92,27 J1.8
  BOTTOM w0.127: U18.7 -2.04,98.54 -2.39,98.19 -2.39,97.77 -2.42,97.74 -2.42,97.59 -2.42,97.59 -2.42,93.15 -2.42,93.14 -2.42,92.23 -2.39,92.2 -2.39,92.04 -1.93,91.58 7.64,91.58 8.24,92.19 U20.2 U20.15 v1(18.67,92.19)
DATA45_S1: length 1.7
  BOTTOM w0.127: U18.8 R43.2
DATA45_S2: length 1.7
  BOTTOM w0.127: R52.2 U20.1
DATA45_S3: length 63.1
  L3_INNER_1 w0.127: v1(26.42,90.24) 25.93,89.75 25.93,68.79 26.48,68.24 26.48,67.55 26.32,67.39 26.32,63.28 29.82,59.78 29.82,55.56 32.85,52.52 v1(32.85,40.57)
  BOTTOM w0.127: v1(26.42,90.24) 26.41,90.25 21.45,90.25 20.78,90.92 U20.16 ; R54.2 v1(32.85,40.57)
DATA67: length 97.5
  L3_INNER_1 w0.127: J1.10 24.46,20.03 22.54,21.96 22.54,48.19 20.13,50.59 20.13,65.84 19.56,66.41 19.56,74.45 19.29,74.73 19.29,92.54 18.7,93.12 v1(18.7,98.54)
  BOTTOM w0.127: v1(18.7,98.54) U20.10 U20.7
DATA67_S1: length 1.7
  BOTTOM w0.127: R50.2 U20.9
DATA67_S2: length 1.7
  BOTTOM w0.127: R44.2 U20.8
DATA_MIC0: length 57.4
  L6_INNER_2 w0.127: v1(35.65,93.46) 35.02,92.84 10.25,92.84 9.04,94.04 6.26,94.04 6.07,94.24 2.64,94.24 -10.53,81.07 v1(-10.53,78.54)
  BOTTOM w0.127: U12.3 v1(35.65,93.46) ; U1.1 v1(-10.53,78.54)
DATA_MIC1: length 77.8
  L3_INNER_1 w0.127: v1(39.46,52.61) 39.46,56.32 41.47,58.34 41.47,93.29 v1(41.3,93.46)
  BOTTOM w0.127: U3.1 6.05,49.86 17.86,49.86 19.2,51.19 34.84,51.19 36.26,52.61 v1(39.46,52.61) ; U12.14 v1(41.3,93.46)
DATA_MIC2: length 68.2
  L3_INNER_1 w0.127: v1(38.59,52.11) 38.59,56.35 40.42,58.18 40.42,81.91 40.16,82.17 40.16,96.15 v1(41.3,97.29)
  BOTTOM w0.127: 38.04,51.12 38.59,51.67 v1(38.59,52.11) ; U15.3 27.92,93.46 28.58,92.81 32.03,92.81 34.61,95.39 39.4,95.39 v1(41.3,97.29) 42.67,97.29 U12.11
DATA_MIC3: length 38.1
  L6_INNER_2 w0.127: v1(38.59,97.27) 39.3,96.56 46.18,96.56 49.71,93.04 49.71,85.35 53.78,81.28 v1(54.34,81.28)
  BOTTOM w0.127: v1(38.59,97.27) U12.6 35.45,97.27 31.64,93.46 U15.14 ; U6.1 v1(54.34,81.28)
DATA_MIC4: length 53.9
  L6_INNER_2 w0.127: v1(36.15,108.09) 36.15,108.08 34.93,106.87 34.75,106.87 33.89,107.73 33.71,107.73 33.53,107.55 33.53,107.37 35.43,105.47 35.43,105.29 35.25,105.11 35.07,105.11 33.17,107.01 32.99,107.01 32.81,106.83 32.81,106.65 34.71,104.75 34.71,104.57 34.53,104.39 34.35,104.39 32.45,106.29 32.27,106.29 32.09,106.11 32.09,105.93 33.99,104.03 33.99,103.85 33.81,103.67 33.63,103.67 31.73,105.57 31.55,105.57 31.37,105.39 31.37,105.21 31.49,105.1 v1(31.49,97.27)
  BOTTOM w0.127: U20.3 14.77,93.46 15.43,94.12 25.47,94.12 28.62,97.27 U15.11 v1(31.49,97.27) ; v1(36.15,108.09) U8.1
DATA_MIC5: length 55.7
  L6_INNER_2 w0.127: v1(5.5,106.93) 5.5,106.37 5.13,105.99 3.39,105.99 3.27,105.87 3.27,105.61 3.39,105.49 6.73,105.49 6.85,105.36 6.85,105.11 6.73,104.98 3.39,104.98 3.27,104.85 3.27,104.6 3.39,104.47 6.73,104.47 6.85,104.34 6.85,104.09 6.73,103.96 3.39,103.96 3.27,103.84 3.27,103.58 3.39,103.45 6.73,103.45 6.85,103.33 6.85,103.07 6.73,102.95 3.39,102.95 3.27,102.82 3.27,102.57 3.39,102.44 6.73,102.44 6.85,102.31 6.85,102.06 6.73,101.93 3.39,101.93 3.27,101.8 3.27,101.55 3.39,101.42 5.38,101.42 5.5,101.3 5.5,97.04 5.91,96.63 7.21,96.63 10.38,93.46 v1(15.9,93.46)
  BOTTOM w0.127: v1(5.5,106.93) 4.8,107.63 U9.1 ; U20.14 v1(15.9,93.46)
DATA_MIC6: length 27.9
  L3_INNER_1 w0.127: v1(22.88,97.27) 22.88,90.06 22.76,89.93 22.37,89.93 22.24,89.8 22.24,89.55 22.37,89.42 22.76,89.42 22.88,89.29 22.88,89.04 22.76,88.91 22.24,88.91 22.12,88.79 22.12,88.53 22.24,88.41 22.76,88.41 22.88,88.28 22.88,88.02 22.76,87.9 22.24,87.9 22.12,87.77 22.12,87.52 22.24,87.39 22.76,87.39 22.88,87.26 22.88,87.01 22.76,86.88 22.24,86.88 22.12,86.75 22.12,86.5 22.24,86.37 22.76,86.37 22.88,86.25 22.88,85.49 22.25,84.86 v1(22.25,82.23)
  BOTTOM w0.127: U10.1 v1(22.25,82.23) ; U15.6 v1(22.88,97.27) U20.11
DATA_MIC7: length 27.2
  L3_INNER_1 w0.127: v1(1.98,81.76) 1.98,76.19 1.75,75.95 0.69,75.95 0.46,76.19 v1(0.46,93.46)
  BOTTOM w0.127: U11.1 2.22,81.99 v1(1.98,81.76) ; U18.3 v1(0.46,93.46)
DATA_MIC8: length 38.3
  L6_INNER_2 w0.127: v1(37.3,81.99) 25.18,81.99 19.67,87.5 14.86,87.5 8.9,93.46 v1(6.07,93.46)
  BOTTOM w0.127: U2.1 v1(37.3,81.99) ; U18.14 v1(6.07,93.46)
DATA_MIC9: length 41.7
  L6_INNER_2 w0.127: v1(6.07,97.27) 9.25,97.27 12.16,100.18 12.16,103.44 14.24,105.52 14.67,105.52 14.92,105.77 14.92,105.95 13.7,107.16 13.7,107.34 13.88,107.52 14.06,107.52 15.28,106.31 15.46,106.31 15.63,106.49 15.63,106.67 14.42,107.88 14.42,108.06 14.6,108.24 14.78,108.24 15.99,107.02 16.17,107.02 16.35,107.2 16.35,107.38 15.14,108.6 15.14,108.78 15.32,108.96 15.5,108.96 16.71,107.74 16.89,107.74 17.07,107.92 17.07,108.1 15.85,109.32 15.85,109.5 16.03,109.68 16.21,109.68 17.43,108.46 17.61,108.46 17.79,108.64 17.79,108.82 16.57,110.04 16.57,110.22 16.75,110.4 16.93,110.4 17.32,110.01 17.5,110.01 v1(19.8,112.3)
  BOTTOM w0.127: U18.11 v1(6.07,97.27) ; U4.1 v1(19.8,112.3)
DATA_MIC10: length 54.3
  L3_INNER_1 w0.127: v1(15.41,64.49) 15.41,96.12 v1(14.26,97.27)
  BOTTOM w0.127: v1(14.26,97.27) U20.6 8.06,97.27 7.4,96.61 3.02,96.61 2.37,97.27 U18.6 ; U7.1 v1(15.41,64.49)
I2C_SCL: length 69
  L3_INNER_1 w0.127: J1.13 28.28,9.19 28.28,16.17 28.73,16.62 28.73,26.1 26.31,28.52 26.31,59.04 24.44,60.9 24.44,72.43 v1(23.81,73.06)
  BOTTOM w0.127: U22.4 23.28,73.15 23.37,73.06 v1(23.81,73.06)
I2C_SDA: length 67
  L3_INNER_1 w0.127: J1.14 29.54,25.92 26.64,28.82 26.64,59.56 24.86,61.34 24.86,72.9 v1(23.81,73.95)
  BOTTOM w0.127: U22.2 v1(23.81,73.95)
N48973005: length 136.3
  L3_INNER_1 w0.127: v1(7.25,99.06) 7.93,99.74 9.17,99.74 9.87,99.05 9.87,85.86 8.01,84.01 v1(8.01,79.64) 8.01,79.64 8.01,61.88 7.62,61.5 7.62,59.22 8.01,58.83 v1(8.01,56.14) 7.56,55.69 7.56,36.75 J6.1
  L6_INNER_2 w0.127: v1(8.01,56.14) 8.03,56.14 8.93,55.25 35.69,55.25 v1(36.18,55.73) ; v1(14.52,79.64) v1(8.01,79.64)
  BOTTOM w0.127: R24.1 33.38,100.82 8.1,100.82 7.25,99.97 R22.1 v1(7.25,99.06) ; J6.1 6.8,36.95 6.7,37.05 R18.2 ; R30.1 v1(14.52,79.64) ; R31.1 v1(36.18,55.73)
N48973061: length 2.1
  BOTTOM w0.127: J6.2 6.8,32.5 6.7,32.4 R33.1
N48974373: length 98.7
  L3_INNER_1 w0.127: v1(45.36,83.26) v1(45.36,99.06) ; J7.1 11.8,36.82 11.8,55.95 12.48,56.63 12.48,66.28 12.25,66.5 v1(12.25,78.2)
  L6_INNER_2 w0.127: v1(45.36,83.26) 45.09,83.54 39.85,83.54 35.96,79.64 v1(28.14,79.64) 27.78,80 24.01,80 22.2,78.2 v1(12.25,78.2)
  BOTTOM w0.127: R19.2 J7.1 ; R23.1 v1(28.14,79.64) ; R25.1 v1(45.36,99.06)
N48974457: length 2.1
  BOTTOM w0.127: R32.1 J7.2
N48975829: length 83.7
  L3_INNER_1 w0.127: v1(16.41,77.73) 16.41,37.26 J8.1
  L6_INNER_2 w0.127: v1(16.41,77.73) 27.69,77.73 28.83,78.87 36.27,78.87 v1(37.03,79.64)
  BOTTOM w0.127: R26.1 45.36,84.86 40.19,79.68 37.08,79.68 v1(37.03,79.64) R28.1 ; R20.2 J8.1
N48975969: length 2.1
  BOTTOM w0.127: R34.1 J8.2
N48976451: length 79.5
  L3_INNER_1 w0.127: v1(34.39,90.17) 34.39,80.15 36.28,78.26 v1(36.28,67.94) ; J9.1 19.32,39.85 18.34,40.84 18.34,67.59 v1(17.55,68.38)
  L6_INNER_2 w0.127: v1(17.55,68.38) 17.76,68.6 35.62,68.6 v1(36.28,67.94)
  BOTTOM w0.127: R21.2 J9.1 ; R29.1 v1(36.28,67.94) ; R27.1 v1(34.39,90.17)
N48976531: length 2.1
  BOTTOM w0.127: R35.1 J9.2
N48977082: length 79.2
  L3_INNER_1 w0.127: J10.1 23.49,39.85 23.02,40.33 23.02,62.58 23.65,63.21 23.65,67.17 v1(23.48,67.34) 23.48,71.27 23.19,71.56 23.19,75.22 23.63,75.66 23.63,97.64 22.22,99.05 21.71,99.05 v1(21.7,99.06)
  L6_INNER_2 w0.127: v1(23.48,67.34) 14.42,67.34 v1(13.76,66.68)
  BOTTOM w0.127: R36.2 J10.1 ; R40.1 v1(21.7,99.06) ; R46.1 v1(13.76,66.68)
N48977084: length 77
  L3_INNER_1 w0.127: v1(26.29,99.21) 26.29,91.25 25.5,90.47 25.5,74.53 25.61,74.42 25.61,73.46 25.5,73.35 v1(25.5,66.68) 25.5,61.83 27.47,59.87 27.47,52.6 28.27,51.8 28.27,40.39 27.66,39.79 J11.1
  BOTTOM w0.127: v1(26.29,99.21) 32.06,99.21 R41.1 ; R47.1 v1(25.5,66.68) ; R37.2 J11.1
N48977086: length 156.7
  L3_INNER_1 w0.127: J12.1 31.84,39.85 31.22,40.47 31.22,53.41 v1(28.89,55.74) 28.89,59.4 25.96,62.33 v1(25.96,67.94) ; v1(5.64,59.91) 5.01,60.55 v1(5.01,67.31) 5.01,79.72 5.55,80.26 5.55,82.87 9,86.33 v1(9,90.17) v1(9,99.06)
  L6_INNER_2 w0.127: v1(28.89,67.94) 35.03,67.94 v1(36.28,66.68) ; v1(28.89,55.74) 28.89,55.73 v1(13.78,55.73) 12.57,55.73 10.93,57.38 8.12,57.38 5.64,59.86 v1(5.64,59.91)
  BOTTOM w0.127: R54.1 R38.2 J12.1 ; R58.1 v1(5.01,67.31) R62.1 ; R57.1 v1(28.89,55.74) ; v1(9,90.17) R52.1 9.14,90.92 9.39,91.17 9.42,91.19 9.46,91.21 9.49,91.21 9.77,91.49 21.14,91.49 R48.1 21.73,90.92 22.34,91.54 32.04,91.54 R42.1 ; R59.1 v1(36.28,66.68) ; R63.1 v1(13.78,55.73) ; v1(9,99.06) R44.1 9.72,100.52 19.24,100.52 R50.1 ; v1(25.96,67.94) R56.1 v1(28.89,67.94)
N48977088: length 116.5
  L3_INNER_1 w0.127: v1(-3.69,90.17) v1(-3.69,79.64) ; J13.1 36.01,39.59 35.47,40.13 35.47,41.26 35.06,41.67 35.06,51.81 34.82,52.05 v1(34.82,54.11) ; v1(6.38,55.73) 6.38,60.58 5.63,61.33 5.63,67.73 v1(6.35,68.44) 5.63,69.16 v1(5.63,79.65)
  L6_INNER_2 w0.127: v1(5.63,79.65) 5.63,79.64 v1(-3.69,79.64) ; v1(34.82,54.11) 8.01,54.11 v1(6.38,55.73) ; v1(13.78,67.94) 13.27,68.44 v1(6.35,68.44)
  BOTTOM w0.127: R51.1 v1(6.38,55.73) ; R39.2 R49.1 J13.1 ; R53.1 v1(13.78,67.94) ; R43.1 -3.69,98.62 -2.68,97.61 -2.68,93.59 -3.69,92.58 R45.1 v1(-3.69,90.17) ; R55.1 v1(5.63,79.65)
N48977384: length 2.1
  BOTTOM w0.127: R60.1 J10.2
N48977390: length 2.1
  BOTTOM w0.127: R61.1 J11.2
N48977416: length 2.1
  BOTTOM w0.127: R65.1 J12.2
N48977422: length 2.1
  BOTTOM w0.127: R64.1 J13.2
N48994161: length 1.9
  BOTTOM w0.127: U35.4 C29.1
N48994166: length 9.4
  L6_INNER_2 w0.127: v1(16.65,24.73) 19.68,24.73 20.19,25.24 22.83,25.24 v1(23.84,24.23)
  BOTTOM w0.127: U35.8 v1(16.65,24.73) ; C29.2 v1(23.84,24.23)
N48994180: length 1.2
  BOTTOM w0.127: U35.6 C28.1
N48994185: length 5.9
  L6_INNER_2 w0.127: v1(21.4,24.73) 20.26,23.58 20.06,23.58 v1(18.34,21.86)
  BOTTOM w0.127: U35.3 v1(21.4,24.73) ; C28.2 v1(18.34,21.86)
N48994280: length 3.1
  TOP w0.127: TP2.1 v1(21.4,25.73)
  BOTTOM w0.127: U35.1 v1(21.4,25.73) 21.79,26.12 R75.1
N48994390: length 1.9
  BOTTOM w0.127: U35.2 R76.2
N48994989: length 1.6
  BOTTOM w0.127: U22.1 23.59,74.35 R73.2
N48996748: length 1.7
  TOP w0.127: D1.C v1(-4.98,65.59)
  BOTTOM w0.127: R66.1 v1(-4.98,65.59)
N48996751: length 1.8
  TOP w0.127: v1(21.71,50.61) 21.73,50.59 D2.C
  BOTTOM w0.127: R67.1 v1(21.71,50.61)
N48996754: length 1.7
  TOP w0.127: D3.C v1(47.85,65.61)
  BOTTOM w0.127: R68.1 v1(47.85,65.61)
N48996757: length 1.7
  TOP w0.127: D4.C v1(46.07,95.96)
  BOTTOM w0.127: R69.1 v1(46.07,95.96)
N48996760: length 1.7
  TOP w0.508: D5.C 22.06,109.07 v1(22.91,109.07)
  BOTTOM w0.508: R70.1 v1(22.91,109.07)
N48996763: length 1.8
  TOP w0.127: D6.C v1(-3.16,95.9)
  BOTTOM w0.127: R71.1 v1(-3.16,95.9)
N48996766: length 2.1
  TOP w0.127: v1(22.51,16.07) 21.46,16.07 D7.C
  BOTTOM w0.127: R72.1 v1(22.51,16.07)
N48996769: length 32.5
  L6_INNER_2 w0.127: v1(-3.22,64.57) 3.23,71.02 18.98,71.02 19.83,71.86 v1(23.85,71.86)
  BOTTOM w0.127: v1(23.85,71.86) 22.96,72.75 U22.5 ; R66.2 v1(-3.22,64.57)
N48996774: length 23.6
  L3_INNER_1 w0.127: v1(22.76,71.14) 22.76,65.93 20.7,63.86 v1(20.7,50.67)
  BOTTOM w0.127: v1(22.76,71.14) 22.45,71.45 22.32,71.45 22.03,71.74 U22.6 ; R67.2 v1(20.7,50.67)
N48996779: length 32.5
  L6_INNER_2 w0.127: v1(20.54,67.84) 23.81,67.84 24.39,67.26 33.47,67.26 35.09,65.64 35.09,65.06 35.58,64.57 v1(46.04,64.57)
  BOTTOM w0.127: R68.2 v1(46.04,64.57) ; v1(20.54,67.84) 20.54,71.32 20.83,71.61 U22.9
N48996784: length 47.5
  L6_INNER_2 w0.127: v1(20.05,71.11) 20.75,70.41 38.74,70.41 46.17,77.84 v1(46.17,93.79)
  BOTTOM w0.127: v1(20.05,71.11) 20.05,71.39 20.43,71.77 U22.10 ; v1(46.17,93.79) 46.18,93.79 R69.2
N48996789: length 35.3
  L3_INNER_1 w0.127: v1(22.07,107.2) 21.2,106.32 21.2,98.49 21.48,98.22 21.48,83.93 21.8,83.61 21.8,81.16 20.07,79.44 20.07,76.55 20.3,76.32 20.3,75.47 v1(19.75,74.92)
  BOTTOM w0.127: U22.15 v1(19.75,74.92) ; R70.2 v1(22.07,107.2)
N48996794: length 42.8
  L3_INNER_1 w0.127: v1(-3.47,93.7) -2.99,93.22 -2.99,76.07 v1(-2.98,76.06)
  L6_INNER_2 w0.127: v1(19.75,76.06) v1(-2.98,76.06)
  BOTTOM w0.127: v1(-3.47,93.7) -3.47,93.7 -3.48,93.71 R71.2 ; v1(19.75,76.06) 20.43,75.39 U22.16
N48996799: length 67.6
  L3_INNER_1 w0.127: v1(17.38,75.55) 17.38,74.5 18.72,73.15 18.72,49.39 20.72,47.4 20.72,24.26 21.09,23.89 21.09,21.23 20.46,20.61 v1(20.46,17.01)
  L6_INNER_2 w0.127: v1(22.21,76.06) 20.64,76.06 20.13,75.55 v1(17.38,75.55)
  BOTTOM w0.127: v1(22.21,76.06) 21.63,75.48 U22.19 ; R72.2 v1(20.46,17.01)
N48996815: length 2.6
  TOP w0.127: TP1.1 23.1,76.95 v1(23.1,76.06)
  BOTTOM w0.127: U22.20 22.03,75.32 22.27,75.56 22.6,75.56 v1(23.1,76.06)
N48996848: length 1.2
  BOTTOM w0.127: U22.12 18.71,73.15 R74.1
N49015950: length 2.3
  BOTTOM w0.127: R2.2 v1(-12.33,77.34) U1.2
N49016109: length 2.4
  BOTTOM w0.127: U6.2 v1(55.16,81.68) R9.2
N49016339: length 2.2
  BOTTOM w0.127: U8.2 v1(36.58,110.26) 36.42,110.41 36.42,110.42 R12.2
N49016430: length 2.2
  BOTTOM w0.127: U9.2 4.21,108.18 v1(3.32,107.28) R13.2
N49016833: length 2
  BOTTOM w0.127: U2.2 v1(36.97,82.81) R4.2
N49016924: length 2
  BOTTOM w0.127: R5.2 v1(19.42,113.12) U4.2
N49017156: length 2
  BOTTOM w0.127: R10.2 v1(19.51,65.31) U7.2
N49017523: length 45.9
  L3_INNER_1 w0.127: v1(25.78,46.8) 25.78,24.15 27.65,22.28 J2.2
  L6_INNER_2 w0.127: v1(8.71,47.15) 25.42,47.15 v1(25.78,46.8)
  BOTTOM w0.127: v1(8.71,47.15) 8.26,47.15 8.18,47.23 R3.1 ; R1.2 J2.2
N49017528: length 2.1
  BOTTOM w0.127: J2.1 R6.1
N49017613: length 2
  BOTTOM w0.127: R3.2 6.75,48 6.75,48 6.17,48.58 v1(6.17,48.58) U3.2
N49017928: length 39.7
  L3_INNER_1 w0.127: J3.2 33.77,24.23 v1(33.77,50.38)
  L6_INNER_2 w0.127: v1(33.77,50.38) 41.13,50.38 v1(41.38,50.63)
  BOTTOM w0.127: R8.1 v1(41.38,50.63) ; R7.2 J3.2
N49017933: length 2.1
  BOTTOM w0.127: J3.1 R11.1
N49018011: length 2
  BOTTOM w0.127: U5.2 38.64,50.54 v1(39.4,51.3) R8.2
N49018485: length 65.9
  L3_INNER_1 w0.127: v1(26.86,79.19) 26.86,76.59 27.22,76.24 27.22,63.59 34.36,56.45 34.36,51.76 34.73,51.39 34.73,48.04 34.51,47.82 34.51,23.78 J4.2
  BOTTOM w0.127: R15.1 26.45,79.61 v1(26.86,79.19) ; R14.2 J4.2
N49018490: length 2.1
  BOTTOM w0.127: J4.1 R17.1
N49018577: length 2
  BOTTOM w0.127: R15.2 v1(23.36,80.63) U10.2
N49018582: length 52.7
  L3_INNER_1 w0.127: v1(9.45,50.73) 9.45,50.72 9.45,47.03 8.96,46.53 8.96,24.44 J5.2
  BOTTOM w0.127: v1(9.45,50.73) 9.56,50.61 14.22,50.61 16.28,52.68 U14.3
N49022344: length 2
  BOTTOM w0.127: U11.2 v1(1.96,82.81) R16.2
N49072543: length 36.8
  L3_INNER_1 w0.127: J14.2 10.97,22.36 9.56,23.77 9.56,40.13 11.05,41.62 v1(11.05,51.74)
  L6_INNER_2 w0.127: J14.2 13.51,24.82 J15.1
  BOTTOM w0.127: U17.1 v1(11.05,51.74)
N49072589: length 34.3
  L3_INNER_1 w0.127: J15.2 12.34,25.09 v1(12.34,51.17)
  BOTTOM w0.127: U17.3 9.15,51.84 9.82,51.17 v1(12.34,51.17)

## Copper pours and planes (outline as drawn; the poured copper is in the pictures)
GND on BOTTOM (solid shape): outline of 769 points within -19.22,0.63 62.06,120.01

Small or netless copper shapes (teardrops, artwork), in the pictures only: 1 on TOP, 1 on L2_GND_1, 1 on L4_PWR_1, 1 on L5_PWR_2

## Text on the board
BOTTOM: 11 | L10_SS | 170-48278 REV B
Board Geometry/Soldermask Bottom: 12 | SECONDARY SOLDERMASK
Ref Des/Silkscreen Bottom: 13 | SECONDARY SILKSCREEN
User.Comments: 1 OF 1 | TEST PROBE | 1/1 | 1
TOP: 04 | L1_PS
Board Geometry/Soldermask Top: 03 | PRIMARY SOLDERMASK
Ref Des/Silkscreen Top: 2MIC,3MICA,3MICC Config: | MIC0,MIC3,MIC6,MIC9 | MIC0 | 6MIC,7MIC,8MIC Config: | MIC4,MIC5,MIC6,MIC10 | MIC0,MIC1,MIC2,MIC3, | 6Mic,7Mic,8Mic   J3 J4 J8 J9 J12 | 4MicB,5Mic       J2 J7 J8 J13 | 2Mic,3MicA,3MicC J6 J9 J10 | 3MicB,4MicA      J7 J9 J10J11 | 8CH-DMIC version 1.0 | MIC10 | MIC6 | MIC9 | 4MIB,5MIB,Config: | MIC1,MIC2,MIC7, | MIC8,MIC10 | MIC0,MIC2,MIC4,MIC6 | 3MICB,4MICA Config: | MIC3 | MIC7 | MIC8 | MIC5 | MIC2 | CLK23 | CLK45 | CLK67 | MIC4 | MIC1 | 02 | PRIMARY SILKSCREEN
L2_GND_1: 05 | L5_GND_1
L3_INNER_1: 06 | L3_INNER_1
L4_PWR_1: 07 | L4_PWR_1
L5_PWR_2: 08 | L5_PWR_2
L6_INNER_2: 09 | L6_INNER_2
L7_GND_2: 10 | L7_GND_2
XSECTION_CHART: *  SURFACE - AIR 0 MIL | *  DIELECTRIC - DRY_FILM_MASK 0.8 MIL | L1 TOP CONDUCTOR - 1OZ_COPPER 1.4 MIL | *  DIELECTRIC - FR-4 2.95 MIL | L2 L2_GND_1 PLANE - 1/2OZ_COPPER 0.63 MIL | *  DIELECTRIC - FR-4 10 MIL | L3 L3_INNER_1 CONDUCTOR - 1/2OZ_COPPER 0.63 MIL | *  DIELECTRIC - FR-4 4.15 MIL | L4 L4_PWR_1 PLANE - 1/2OZ_COPPER 0.63 MIL | *  DIELECTRIC - FR-4 18 MIL | L5 L5_PWR_2 PLANE - 1/2OZ_COPPER 0.63 MIL | L6 L6_INNER_2 CONDUCTOR - 1/2OZ_COPPER 0.63 MIL | L7 L7_GND_2 PLANE - 1/2OZ_COPPER 0.63 MIL | L8 BOTTOM CONDUCTOR - 1OZ_COPPER 1.4 MIL | DESIGN CROSS SECTION CHART | ___________________________ | TOTAL THICKNESS 60.38 MIL | 1-8 | LAYERS | L1_PS | L3_INNER_1 | L6_INNER_2 | L8_SS | TRACE WIDTH | 5.00 | SE | IMPEDANCE | 50.00 | REFERENCE LAYER | 2,4 | 5,7 | 2 | 7 | BOARD THICKNESS TOLERANCE +/-10% | SCALE: NONE | 8 | 19 | 16 | DETAIL | LAYER STACKUP | IMPEDANCE REQUIREMENTS | IMPEDANCE TOLERANCE IS 10% | A | B
DIMENSION: PRIMARY DATUM | GRID ORIGIN
BODY_CENTER: 01 | PASTEMASK TOP
DISPLAY_BOTTOM: 14 | SECONDARY PASTEMASK
User.11: OF 14
User.14: 22. THIS FAB_VIAFILL.ART SHOWS LOCATIONS OF VIA-IN-PAD TO BE FILLED. | 1/1 | 2 | 3
User.15: 24. | 1/1 | 3 | CAD DESIGNER: DELETE THIS FAB PAGE IF BACKDRILL IS NOT USED ON THIS DESIGN. | FAB SUPPLIER: DISREGARD THIS PAGE IF BACKDRILL REQUIRMENT IS NOT PROVIDED.
User.16: 02-19-21 | D.V. | B | CHANGES PER ECO141058
